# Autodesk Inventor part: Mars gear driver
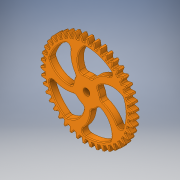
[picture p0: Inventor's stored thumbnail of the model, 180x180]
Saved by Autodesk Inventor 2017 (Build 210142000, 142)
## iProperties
Created: 2016-05
Part Number: Mars gear driver
Material: Generic
Document SubType Name: Modeling
Designer: Stan
Density: 1 g/cm^3
Appearance: Orange
Author: Stan
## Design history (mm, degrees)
sketch "Sketch1"
  geometry: A1 r 19.695 centre (11.709, 37.538) between (-7.162, 43.176) and (-7.935, 38.961); A2 r 19.695 centre (-26.535, 29.019) between (-9.353, 38.645) and (-11.841, 42.134); A3 r 19.695 centre (6.118, 38.843) between (-13.372, 41.673) and (-13.523, 37.39); A4 r 19.695 centre (-30.477, 24.846) between (-14.88, 36.872) and (-17.85, 39.961); A5 r 19.695 centre (0.398, 39.32) between (-19.298, 39.282) and (-18.823, 35.023); A6 r 19.695 centre (-33.77, 20.144) between (-20.09, 34.312) and (-23.478, 36.936); A7 r 19.695 centre (-5.332, 38.959) between (-24.811, 36.054) and (-23.722, 31.909); A8 r 19.695 centre (-36.343, 15.012) between (-24.871, 31.021) and (-28.606, 33.124); A9 r 19.695 centre (-10.947, 37.767) between (-29.796, 32.057) and (-28.115, 28.115); A10 r 19.695 centre (-38.142, 9.561) between (-29.123, 27.07) and (-33.124, 28.606); A11 r 19.695 centre (-16.33, 35.771) between (-34.146, 27.377) and (-31.909, 23.722); A12 r 19.695 centre (-39.127, 3.905) between (-32.754, 22.541) and (-36.936, 23.478); A13 r 19.695 centre (-21.364, 33.012) between (-37.769, 22.113) and (-35.023, 18.823); A14 r 19.695 centre (-39.279, -1.833) between (-35.687, 17.531) and (-39.961, 17.85); A15 r 19.695 centre (-25.943, 29.55) between (-40.586, 16.379) and (-37.39, 13.523); A16 r 19.695 centre (-38.594, -7.533) between (-37.859, 12.149) and (-42.134, 11.841); A17 r 19.695 centre (-29.969, 25.458) between (-42.538, 10.295) and (-38.961, 7.935); A18 r 19.695 centre (-37.085, -13.072) between (-39.225, 6.507) and (-43.409, 5.581); A19 r 19.695 centre (-33.356, 20.823) between (-43.584, 3.991) and (-39.701, 2.178); A20 r 19.695 centre (-34.787, -18.332) between (-39.754, 0.726) and (-43.759, -0.799); A21 r 19.695 centre (-36.032, 15.744) between (-43.7, -2.397) and (-39.595, -3.626); A22 r 19.695 centre (-31.747, -23.202) between (-39.436, -5.07) and (-43.176, -7.162); A23 r 19.695 centre (-37.941, 10.33) between (-42.886, -8.734) and (-38.645, -9.353); A24 r 19.695 centre (-28.03, -27.577) between (-38.278, -10.758) and (-41.673, -13.372); A25 r 19.695 centre (-39.04, 4.696) between (-41.157, -14.885) and (-36.872, -14.88); A26 r 19.695 centre (-23.717, -31.365) between (-36.304, -16.216) and (-39.282, -19.298); A27 r 19.695 centre (-39.308, -1.039) between (-38.551, -20.719) and (-34.312, -20.09); A28 r 19.695 centre (-18.897, -34.483) between (-33.556, -21.329) and (-36.054, -24.811); A29 r 19.695 centre (-38.738, -6.751) between (-35.124, -26.112) and (-31.021, -24.871); A30 r 19.695 centre (-13.675, -36.867) between (-30.092, -25.988) and (-32.057, -29.796); A31 r 19.695 centre (-37.342, -12.319) between (-30.947, -30.947) and (-27.07, -29.123); A32 r 19.695 centre (-8.161, -38.466) between (-25.988, -30.092) and (-27.377, -34.146); A33 r 19.695 centre (-35.151, -17.625) between (-26.112, -35.124) and (-22.541, -32.754); A34 r 19.695 centre (-2.474, -39.244) between (-21.329, -33.556) and (-22.113, -37.769); A35 r 19.695 centre (-32.21, -22.555) between (-20.719, -38.551) and (-17.531, -35.687); A36 r 19.695 centre (3.267, -39.186) between (-16.216, -36.304) and (-16.379, -40.586); A37 r 19.695 centre (-28.582, -27.005) between (-14.885, -41.157) and (-12.149, -37.859); A38 r 19.695 centre (8.937, -38.293) between (-10.758, -38.278) and (-10.295, -42.538); A39 r 19.695 centre (-24.346, -30.878) between (-8.734, -42.886) and (-6.507, -39.225); A40 r 19.695 centre (14.418, -36.583) between (-5.07, -39.436) and (-3.991, -43.584); A41 r 19.695 centre (-19.591, -34.094) between (-2.397, -43.7) and (-0.726, -39.754); A42 r 19.695 centre (19.591, -34.094) between (0.726, -39.754) and (2.397, -43.7); A43 r 19.695 centre (-14.418, -36.583) between (3.991, -43.584) and (5.07, -39.436); A44 r 19.695 centre (24.346, -30.878) between (6.507, -39.225) and (8.734, -42.886); A45 r 19.695 centre (-8.937, -38.293) between (10.295, -42.538) and (10.758, -38.278); A46 r 19.695 centre (28.582, -27.005) between (12.149, -37.859) and (14.885, -41.157); A47 r 19.695 centre (-3.267, -39.186) between (16.379, -40.586) and (16.216, -36.304); A48 r 19.695 centre (32.21, -22.555) between (17.531, -35.687) and (20.719, -38.551); A49 r 19.695 centre (2.474, -39.244) between (22.113, -37.769) and (21.329, -33.556); A50 r 19.695 centre (35.151, -17.625) between (22.541, -32.754) and (26.112, -35.124); A51 r 19.695 centre (8.161, -38.466) between (27.377, -34.146) and (25.988, -30.092); A52 r 19.695 centre (37.342, -12.319) between (27.07, -29.123) and (30.947, -30.947); A53 r 19.695 centre (13.675, -36.867) between (32.057, -29.796) and (30.092, -25.988); A54 r 19.695 centre (38.738, -6.751) between (31.021, -24.871) and (35.124, -26.112); A55 r 19.695 centre (18.897, -34.483) between (36.054, -24.811) and (33.556, -21.329); A56 r 19.695 centre (39.308, -1.039) between (34.312, -20.09) and (38.551, -20.719); A57 r 19.695 centre (23.717, -31.365) between (39.282, -19.298) and (36.304, -16.216); A58 r 19.695 centre (39.04, 4.696) between (36.872, -14.88) and (41.157, -14.885); A59 r 19.695 centre (28.03, -27.577) between (41.673, -13.372) and (38.278, -10.758); A60 r 19.695 centre (37.941, 10.33) between (38.645, -9.353) and (42.886, -8.734); A61 r 19.695 centre (31.747, -23.202) between (43.176, -7.162) and (39.436, -5.07); A62 r 19.695 centre (36.032, 15.744) between (39.595, -3.626) and (43.7, -2.397); A63 r 19.695 centre (34.787, -18.332) between (43.759, -0.799) and (39.754, 0.726); A64 r 19.695 centre (33.356, 20.823) between (39.701, 2.178) and (43.584, 3.991)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; 1 further point
  constraints: 344 point on circle, 172 centre point, 4 horizontal alignment, 512 other
  dimensions: "d0" = 0 dimension on point (0, 0); "d1" = 0 dimension on point (0, 0)
extrude "Extrusion1" new body sketch "Sketch1" distance "d2" = 6.35; taper "d3" = 0 deg
sketch "Sketch2"
  geometry: C1 r 3.175 at (0, 0); 1 further point
  constraints: 1 centre point, 1 coincident
  dimensions: "d4" = 6.35 diameter of C1
extrude "Extrusion2" cut sketch "Sketch2" distance "d5" = 6.35; taper "d6" = 0 deg
sketch "Sketch3"
  geometry: A1 r 36.513 centre (0, 0) between (-8.745, -35.45) and (22.733, -28.572); A2 r 36.513 centre (0, 0) between (31.012, -19.272) and (34.199, 12.791); A3 r 36.513 centre (0, 0) between (27.912, 23.539) and (-1.597, 36.478); A4 r 36.513 centre (0, 0) between (-13.762, 33.82) and (-35.111, 10.018); A5 r 36.513 centre (0, 0) between (-36.417, -2.638) and (-19.934, -30.591); A6 r 26.136 centre (10.543, 24.21) between (-13.762, 33.82) and (-9.912, 7.941); A7 r 19.198 centre (10.719, 21.75) between (-1.597, 36.478) and (-5.485, 11.455); A8 r 26.136 centre (-19.767, 17.508) between (-36.417, -2.638) and (-10.615, -6.973); A9 r 19.198 centre (-17.211, 16.957) between (-35.111, 10.018) and (-12.589, -1.677); A10 r 26.136 centre (-22.445, -13.193) between (-8.745, -35.45) and (3.67, -12.158); A11 r 19.198 centre (-21.466, -11.454) between (-19.934, -30.591) and (-2.295, -12.491); A12 r 26.136 centre (5.701, -25.783) between (31.012, -19.272) and (12.686, -0.598); A13 r 19.198 centre (4.113, -23.897) between (22.733, -28.572) and (11.17, -6.043); A14 r 26.136 centre (26.283, -2.546) between (27.912, 23.539) and (4.489, 11.88); A15 r 19.198 centre (23.998, -3.473) between (34.199, 12.791) and (9.199, 8.756); A16 r 12.7 centre (0, 0) between (4.489, 11.88) and (-5.485, 11.455); A17 r 12.7 centre (0, 0) between (12.686, -0.598) and (9.199, 8.756); A18 r 12.7 centre (0, 0) between (3.67, -12.158) and (11.17, -6.043); A19 r 12.7 centre (0, 0) between (-9.912, 7.941) and (-12.589, -1.677); A20 r 12.7 centre (0, 0) between (-10.615, -6.973) and (-2.295, -12.491); 1 further point
  constraints: 40 point on circle, 20 centre point
  dimensions: "d7" = 0 distance of point (0, 0) A1.centre; "d8" = 0 distance of A1.centre point (0, 0); "d9" = 36.5125 radius of A3; "d10" = 36.5125 radius of A2; "d11" = 36.5125 radius of A1; "d12" = 36.5125 radius of A5; "d13" = 36.5125 radius of A4
extrude "Extrusion3" cut sketch "Sketch3" distance "d15" = 6.35; taper "d16" = 0 deg
fillet "Fillet1" dims "d17" = 3.175
fillet "Fillet2" dims "d18" = 3.175
fillet "Fillet3" dims "d19" = 0.762
fillet "Fillet4" dims "d20" = 0.762
fillet "Fillet6" dims "d25" = 0.79375
fillet "Fillet7" dims "d26" = 0.79375
fillet "Fillet8" dims "d27" = 0.79375
fillet "Fillet9" dims "d28" = 0.79375
body "Solid1"
other parameters: "d14" = 25.4
